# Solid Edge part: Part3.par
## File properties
Author: Deepak Maini
Template: Normal.par
Last saved by: Robert a Rhodes jr
Revision: 2
Application: Solid Edge
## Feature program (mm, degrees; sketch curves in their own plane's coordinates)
sketch for "unnamed Protrusion 1" #1 plane through (0, 0, 0) normal (0, 0, 1) x-axis (1, 0, 0)
  line (-42.48, -13.536) -> (53.136, -13.536)
  arc centre (53.136, -1.872) radius 11.664 from (53.136, 9.792) to (53.136, -13.536) cw
  line (53.136, 9.792) -> (-42.48, 9.792)
  arc centre (-42.48, -1.872) radius 11.664 from (-42.48, 9.792) to (-42.48, -13.536) ccw
sketch for "unnamed Protrusion 1" #2 plane through (0, 0, 0) normal (0, 0, 1) x-axis (1, 0, 0)
  circle centre (-42.48, -1.872) radius 7
sketch for "unnamed Protrusion 1" #3 plane through (0, 0, 0) normal (0, 0, 1) x-axis (1, 0, 0)
  circle centre (53.136, -1.872) radius 7
extrude "unnamed Protrusion 1" add finite 13 along -normal
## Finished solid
Body 1: solid body, 8 faces, 16 edges, 8 vertices.
  Faces by surface: cylinder 4, plane 4
  Edges by curve: circle 8, line 8
Bounding box of the edges (mm): 118.944 x 23.328 x 13.000, from (-54.144, -13.536, -13) to (64.8, 9.792, 0).
Cylindrical faces by radius (mm): R7 x2, R11.664 x2
Planar faces by outward normal: +y 1, +z 1, -y 1, -z 1
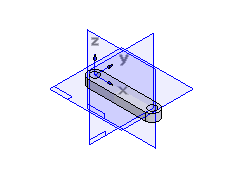
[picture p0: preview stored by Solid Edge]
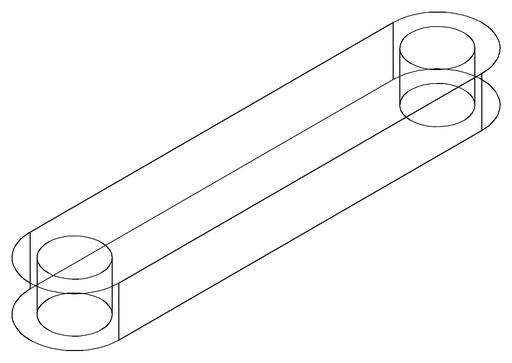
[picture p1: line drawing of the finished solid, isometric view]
